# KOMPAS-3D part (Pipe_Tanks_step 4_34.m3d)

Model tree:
1. X Axis
2. Y Axis
3. Z Axis  (labels: Valve Dy 50; Pipe Dn 50)
     Òîëùèíà ñòåíêè 1 = 1

Referenced files in C:\Documents and Settings\kashirsky\Мои документы\Camtasia Studio\Pipelines3D\Tanks\: Tanks_step 4.a3d
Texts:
  Pipe Dn 50
  Steel ASTM A295
  Three Point Plane
  Plane at Angle
  Line and Point Plane
  Axis through Two Vertices
  Axis of Feature
  Axis of Conical Surface
  Axis through Edge
  Trim by Surface
  Trim by Sketch
  Feature with No History
  Intersection Axis of Two Planes
  Two Line Plane
  Line and Face Plane
  Bend by line
  Hole in sheet body
  Cut in sheet body
  Point in CM
  Linear Dimension from Line to Point
  Surface Finish Symbol
  Geometric Tolerance Symbol
  Leader #1
  Leader #2
  Leader #3
  Shape Deviations and Datum
  Node point number
  Mark of coordination axis
  Node point designation
  Mark/Reference designation with leader
  Mark/reference designation on line
  Mark/Reference designation without leader
  Valve Dy 50
  Plane of section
